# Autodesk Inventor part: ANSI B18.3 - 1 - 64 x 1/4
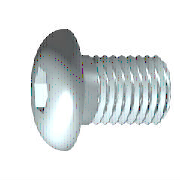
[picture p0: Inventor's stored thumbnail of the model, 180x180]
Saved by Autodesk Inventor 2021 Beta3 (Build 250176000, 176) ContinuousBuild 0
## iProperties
Created: 2012-02
Part Number: ANSI B18.3 - 1 - 64 x 1/4
Material: Generic
Description: Hexagon Socket Button Head Cap Screw
Document SubType Name: Modeling
Standard: ANSI B18.3
Designer: John
Standard Revision: 2003
Standards Organization: ANSI
Language: en-US
Size Designation: 1 - 64 x 1/4
Categories: <MemberInstance><Categories><Category DisplayName="Fasteners" InternalName="e4da775c-781d-43d5-af7c-5136215cf5a6" Mnemonic="FSTN"><Category DisplayName="Bolts"
Density: 1 g/cm^3
Appearance: Default
IsCustomPart: 0
Author: John
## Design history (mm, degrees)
sketch "Sketch1"
  geometry: L1 (0.144, 0)-(6.35, 0); L2 (6.35, 0)-(6.35, 0.927); L3 (6.35, 0.927)-(0.793, 0.927); L4 (0.793, 0.927)-(0, 0.927); L5 (0, 0.927)-(0, 0.927); L6 (0, 0.927)-(0, 1.765); L7 (0, 1.765)-(-0.991, 1.765); L8 (-0.991, 1.765)-(-0.991, 0.733); L9 (-0.991, 0.733)-(-0.279, 0.733); L10 (-0.279, 0.733)-(0.144, 0); L11 (-2.459, 0)-(7.818, 0) reference; L12 (0, -0.353)-(0, 2.118) reference; L13 (0.793, 0.927)-(0, 0.927)
  constraints: 22 end point, 6 parallel, 2 collinear, 2 perpendicular, 1 horizontal, 1 point on line
  dimensions: "d1" = 5.55732 distance from line of L3.end L2 (= GEL); "d2" = 0.79258 distance of L4.end L3.end (computed from GAL); "d3" = 0.9906 distance between parallel lines of L8 L6 (= KOH); "d4" = 0.7112 distance of L8.end L9.end (= INTI); "d5" = 60 deg angle of L10 L1; "d6" = 1.8542 diameter of L3 L1 (= GD); "d7" = 1.8542 diameter of L5 L1 (= BDM); "d8" = 1.46647 diameter of L9 L1 (= 1.1547 x SW); "d9" = 3.5306 diameter of L7 L1 (= KOD); "d26" = 6.35 distance between parallel lines of L12 L2 (= NLG)
revolve "Body" sketch "Sketch1" stored, may be unused: angle "d10" = 90 deg
sketch "Sketch2"
  geometry: L1 (0, -2.471)-(0, 2.471) reference; L2 (-2.471, 0)-(2.471, 0) reference; L3 (0.733, 0)-(0.367, -0.635); L4 (0.367, -0.635)-(-0.367, -0.635); L5 (-0.367, -0.635)-(-0.733, 0); L6 (-0.733, 0)-(-0.367, 0.635); L7 (-0.367, 0.635)-(0.367, 0.635); L8 (0.367, 0.635)-(0.733, 0); 2 further points
  constraints: 12 end point, 1 coincident, 1 horizontal alignment, 1 point on line, 12 other
extrude "Slot" join sketch "Sketch2" stored distance "d11" = 10; taper "d12" = 0 deg
workplane "Work Plane1"
fillet "Fillet2" dims "d30" = 0.1 (= R)
body "Solid1"
fillet "Fillet1" dims "d17" = 0.9905 (= RR)
feature "Thread" dims "d13" = 5.55732 (= GEL), "d14" = 0
chamfer "Chamfer1" distance "d15" = 0.24346 (= -0.5 x SPD + 0.5 x GD); stored, may be unused: second distance "d16" = 0.24333 (= GUL), angle "d27" = 45 deg
other parameters: "GD" = 1.8542 (= NND) [user parameter; used in 2 equation terms], "NLG" = 6.35 [user parameter; used in 1 equation term], "GEL" = 5.55732 [user parameter; used in 2 equation terms], "KOD" = 3.5306 [user parameter; used in 1 equation term], "KOH" = 0.9906 [user parameter; used in 1 equation term], "INTI" = 0.7112 [user parameter; used in 1 equation term], "GAL" = 0.79248 [user parameter; used in 1 equation term], "GUL" = 0.24333 [user parameter; used in 1 equation term], "BDM" = 1.8542 (= NND) [user parameter; used in 1 equation term], "SW" = 1.27 [user parameter; used in 1 equation term], "RR" = 0.9905 [user parameter; used in 1 equation term], "SPD" = 1.36728 [user parameter; used in 2 equation terms], "d19" = 0, "d28" = 0, "d29" = 0, "R" = 0.1 [user parameter; used in 1 equation term], "TOA" = 30 deg [user parameter], "GD1" = 1.36728 (= SPD) [user parameter], "THREADDIA" = 1.8542 [user parameter], "PTC" = 0.39687 (computed from TPU) [user parameter], "KOH1" = 0.254 [user parameter], "NND" = 1.8542 [user parameter; used in 2 equation terms], "E0" = 1.46685 [user parameter]
